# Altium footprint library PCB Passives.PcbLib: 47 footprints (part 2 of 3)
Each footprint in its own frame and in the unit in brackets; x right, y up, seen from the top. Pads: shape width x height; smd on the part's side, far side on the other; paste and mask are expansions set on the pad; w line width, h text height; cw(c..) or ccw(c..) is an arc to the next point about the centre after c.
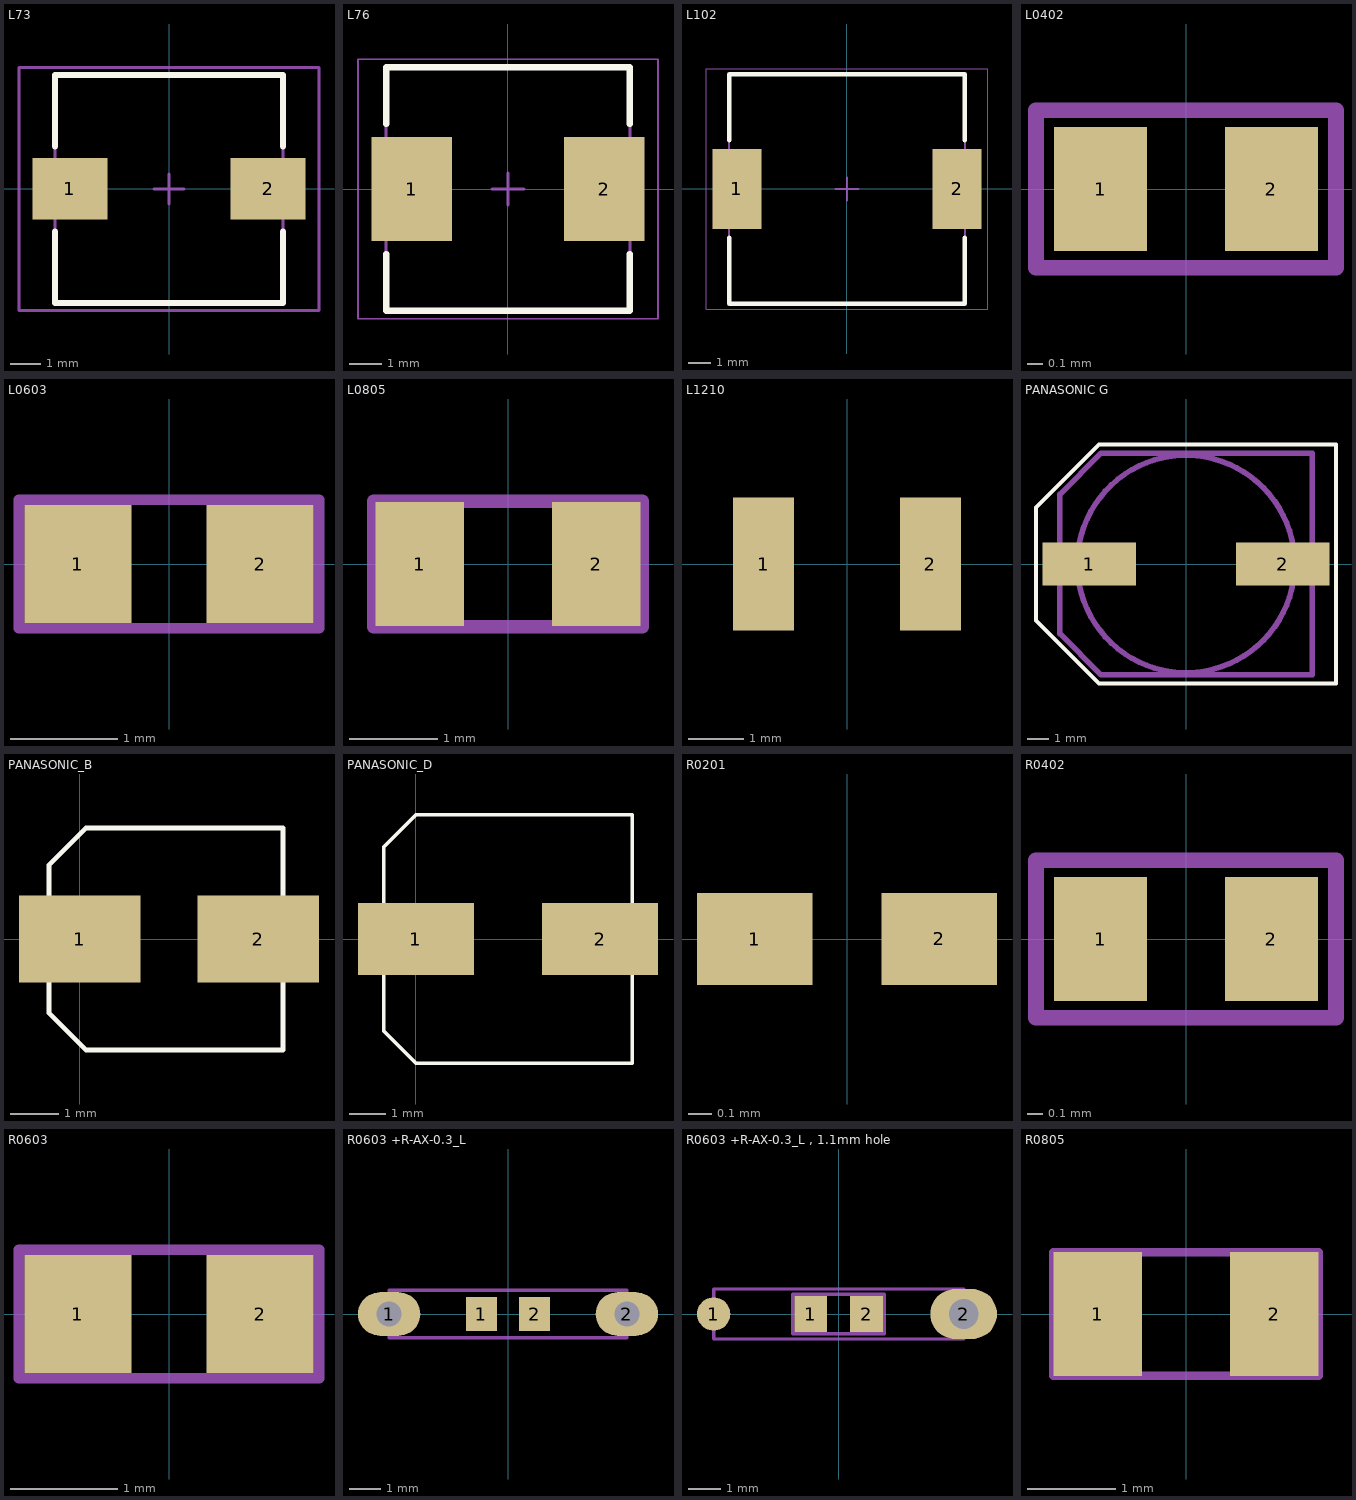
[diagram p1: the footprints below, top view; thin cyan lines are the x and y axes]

## L73 [mm] "Inductor 7.3x7.3mm"
height 3.55
pads (2):
  rect 2.5x2.05 smd: 1(-3.3,0) 2(3.3,0)
Top Overlay:
  lines w0.2: -3.8,-1.425 -3.8,-3.8 3.8,-3.8 3.8,-1.425 ; -3.8,1.425 -3.8,3.8 3.8,3.8 3.8,1.425
Mechanical 13:
  lines w0.1: -3.8,-3.8 3.8,-3.8 3.8,3.8 -3.8,3.8 -3.8,-3.8
Mechanical 15:
  lines w0.1: -0.5,0 0.5,0 ; 0,-0.5 0,0.5 ; -5,-4.05 5,-4.05 5,4.05 -5,4.05 -5,-4.05
3D body "User Library-Murata_4600.step": height 4.55, standoff 0, extent -3.764,-3.65 3.664,3.65

## L76 [mm] "Inductor 7.6x7.6 mm"
height 3.55
pads (2):
  rect 2.5x3.25 smd: 1(-3,0) 2(3,0)
Top Overlay:
  lines w0.2: -3.8,-2.025 -3.8,-3.8 3.8,-3.8 3.8,-2.025 ; -3.8,2.025 -3.8,3.8 3.8,3.8 3.8,2.025
Mechanical 13:
  lines w0.1: -3.8,-3.8 -3.8,3.8 3.8,3.8 3.8,-3.8 -3.8,-3.8
Mechanical 15:
  lines w0.05: -4.675,-4.05 -4.675,4.05 4.675,4.05 4.675,-4.05 -4.675,-4.05
  lines w0.1: -0.5,0 0.5,0 ; 0,-0.5 0,0.5
3D body "dra73.STEP": height 3.56, standoff 0, extent -3.8,-3.8 3.8,3.8

## L102 [mm] "Inductor 10.2x10.2 mm"
height 4
pads (2):
  rect 2.2x3.56 smd: 1(-4.9,0) 2(4.9,0)
Top Overlay:
  lines w0.2: -5.25,-2.18 -5.25,-5.1 5.25,-5.1 5.25,-2.18 ; -5.25,2.18 -5.25,5.1 5.25,5.1 5.25,2.18
Mechanical 13:
  lines w0.1: -5.25,-5.1 5.25,-5.1 5.25,5.1 -5.25,5.1 -5.25,-5.1
Mechanical 15:
  lines w0.05: -6.275,-5.35 6.275,-5.35 6.275,5.35 -6.275,5.35 -6.275,-5.35
  lines w0.1: -0.5,0 0.5,0 ; 0,-0.5 0,0.5
3D body "Coilcraft-MSS1038.step": height 4, standoff 0, extent -5.15,-5.2 5.15,5

## L0402 [mm] "0402 inductor"
pads (2):
  rect 0.6x0.8 smd: 1(-0.55,0) 2(0.55,0)
Mechanical 29:
  lines w0.1: -0.965,-0.508 0.965,-0.508 0.965,0.508 -0.965,0.508 -0.965,-0.508
  text ".Designator" at -0.787,-0.279 h0.6
3D body "User Library-Chip Inductor(1).step": height 0.49, standoff -0.01, extent -0.5,-0.3 0.5,0.3

## L0603 [mm] "0603 inductor"
pads (2):
  rect 1x1.1 smd: 1(-0.85,0) 2(0.85,0)
Mechanical 29:
  lines w0.1: -1.4,-0.6 -1.4,0.6 1.4,0.6 1.4,-0.6 -1.4,-0.6
  text ".Designator" at -1.1,-0.2 h0.6
3D body "User Library-Chip Inductor.step": height 0.79, standoff -0.01, extent -0.8,-0.5 0.8,0.45

## L0805 [mm] "0805 inductor"
pads (2):
  rect 1x1.4 smd: 1(-1,0) 2(1,0)
Mechanical 29:
  lines w0.15: -1.524,-0.711 1.524,-0.711 1.524,0.711 -1.524,0.711 -1.524,-0.711
  text ".Designator" at -0.635,-0.254 h0.51
3D body "User Library-Chip Inductor(2).step": height 0.94, standoff -0.01, extent -1,-0.6 1,0.6

## L1210 [mm] "1210 inductor"
pads (2):
  rect 1.1x2.4 smd: 1(-1.5,0) 2(1.5,0)
3D body "User Library-Chip Inductor(3).step": height 2, standoff 0, extent -1.25,-1.1 1.25,1.1

## PANASONIC G [mm]
pads (2):
  rect 4.3x2 smd: 1(-4.45,0) 2(4.45,0)
Top Overlay:
  lines w0.2: -6.9,-2.6 -4,-5.5 6.9,-5.5 6.9,5.5 -4,5.5 -6.9,2.6 -6.9,-2.6
Mechanical 13:
  circle w0.254: c0,0 r5
  lines w0.254: -5.8,-3.2 -5.8,3.2 -3.9,5.1 5.8,5.1 5.8,-5.1 -3.9,-5.1 -5.8,-3.2
3D body "User Library-cap_10x10x10-1.STEP": height 10.5, standoff 0, extent -5.901,-5.25 5.899,5.25

## PANASONIC_B [mm]
pads (2):
  rect 2.5x1.8 smd: 1(0,0) 2(3.683,0)
Top Overlay:
  lines w0.1: -0.635,-1.524 0.127,-2.286 4.191,-2.286 4.191,2.286 0.127,2.286 -0.635,1.524 -0.635,-1.524
3D body "CAPAE-D4.0x5.4.stp": height 5.5, standoff 0, extent -0.95,-2.25 4.55,2.25

## PANASONIC_D [mm]
pads (2):
  rect 3.2x2 smd: 1(0,0) 2(5.08,0)
Top Overlay:
  lines w0.1: -0.889,-2.54 -0.889,2.54 0,3.429 5.969,3.429 5.969,-3.429 0,-3.429 -0.889,-2.54
3D body "CAPAE-D6.3x5.4.stp": height 5.5, standoff 0, extent -1.35,-3.4 6.45,3.4

## R0201 [mm] "0201 resistor"
pads (2):
  rect 0.5x0.4 smd: 1(-0.4,0) 2(0.4,0)
3D body "User Library-SMD RESISTOR-1.step": height 0.22, standoff -0.01, extent -0.3,-0.15 0.3,0.15

## R0402 [mm] "0402 resistor"
pads (2):
  rect 0.6x0.8 smd: 1(-0.55,0) 2(0.55,0)
Mechanical 29:
  lines w0.1: -0.965,-0.508 -0.965,0.508 0.965,0.508 0.965,-0.508 -0.965,-0.508
  text ".Designator" at -0.787,-0.279 h0.6
3D body "RES_0402.step": height 0.34, standoff -0.01, extent -0.5,-0.246 0.5,0.254

## R0603 [mm] "0603 resistor"
pads (2):
  rect 1x1.1 smd: 1(-0.85,0) 2(0.85,0)
Mechanical 29:
  lines w0.1: -1.4,-0.6 -1.4,0.6 1.4,0.6 1.4,-0.6 -1.4,-0.6
  text ".Designator" at -1.2,-0.2 h0.6
3D body "RES_0603.step": height 0.45, standoff -0.01, extent -0.8,-0.4 0.8,0.4

## R0603 +R-AX-0.3_L [mm] "0603 resistor with THT pads"
pads (4):
  oval 2x1.4 hole 0.8: 1(-3.81,0) 2(3.81,0)
  rect 1x1.1 smd: 1(-0.85,0) 2(0.85,0)
Mechanical 29:
  lines w0.102: -3.81,-0.762 3.81,-0.762 3.81,0.762 -3.81,0.762 -3.81,-0.762
  text ".Designator" at -1.2,-0.2 h0.6
3D body "RES_0603.step": height 0.45, standoff -0.01, extent -0.8,-0.4 0.8,0.4

## R0603 +R-AX-0.3_L , 1.1mm hole [mm] "0603 resistor with THT pads"
pads (4):
  round 1.016 all layers, no hole: 1(-3.81,0)
  rect 1x1.1 smd: 1(-0.85,0) 2(0.85,0)
  oval 2.032x1.524 hole 0.9: 2(3.81,0)
Mechanical 29:
  lines w0.1: -1.4,-0.6 -1.4,0.6 1.4,0.6 1.4,-0.6 -1.4,-0.6
  lines w0.102: -3.81,-0.762 -3.81,0.762 3.81,0.762 3.81,-0.762 -3.81,-0.762
  text ".Designator" at -1.2,-0.2 h0.6
3D body "RES_0603.step": height 0.45, standoff -0.01, extent -0.8,-0.4 0.8,0.4

## R0805 [mm] "0805 resistor"
pads (2):
  rect 1x1.4 smd: 1(-1,0) 2(1,0)
Mechanical 29:
  lines w0.1: -1.5,-0.7 1.5,-0.7 1.5,0.7 -1.5,0.7 -1.5,-0.7
  text ".Designator" at -1.3,-0.2 h0.6
3D body "RES_0805.step": height 0.6, standoff 0, extent -1,-0.625 1,0.625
